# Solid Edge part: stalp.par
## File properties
Author: User
Template: iso metric part.par
Last saved by: User
Revision: 2
Application: Solid Edge
Accuracy: 0.990
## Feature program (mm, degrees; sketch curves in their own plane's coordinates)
sketch for "unnamed Protrusion 1" plane through (0, 0, 0) normal (0, 0, 1) x-axis (1, 0, 0)
  circle centre (0, 0) radius 8
extrude "unnamed Protrusion 1" add finite 130 along +normal
sketch for "ExtrudedProtrusion_2" plane through (0, 0, 130) normal (0, 0, 1) x-axis (1, 0, 0)
  circle centre (0, 0) radius 3.5
extrude "ExtrudedProtrusion_2" add finite 8 along +normal
sketch for "ExtrudedCutout_1" plane through (0, 0, 0) normal (0, 0, -1) x-axis (1, 0, 0)
  line (5, 6.801) -> (5, -7.7448)
extrude "ExtrudedCutout_1" cut finite 12 along -normal
mirror "unnamed Mirror 1" of "ExtrudedCutout_1" about plane through (0, 0, 0) normal (1, 0, 0)
extrude "unnamed Cutout 1" cut finite 12
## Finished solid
Body 1: solid body, 9 faces, 15 edges, 8 vertices.
  Faces by surface: plane 7, cylinder 2
  Edges by curve: line 8, circle 7
Bounding box of the edges (mm): 16.000 x 16.000 x 138.000, from (-8, -8, 0) to (8, 8, 138).
Cylindrical faces by radius (mm): R3.5 x1, R8 x1
Planar faces by outward normal: +x 1, +z 2, -x 1, -z 3
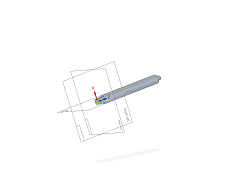
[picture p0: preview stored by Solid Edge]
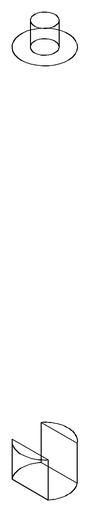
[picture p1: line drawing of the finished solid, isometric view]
